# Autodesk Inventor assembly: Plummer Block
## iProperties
Shininess: 64.0
Length Units: 11269
Angle Units: 11279
Time Units: 11290
Mass Units: 11283
Length Display Precision: 3
Angle Display Precision: 2
Created: 2002-02
Part Number: Plummer Block
Document SubType Name: Assembly
Designer: ***
Density: 0.0
Volumn: 0.0
Area: 0.0
PropertySet Name: Model Information
Control State: 0
Master: False
Checked Out: False
Author: ***
